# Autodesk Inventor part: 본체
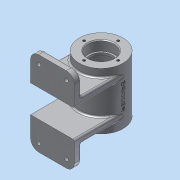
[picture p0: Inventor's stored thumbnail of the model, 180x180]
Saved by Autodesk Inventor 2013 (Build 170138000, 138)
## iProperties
Created: 2017-02
Part Number: 본체
Material: 알루미늄 6061
Document SubType Name: Modeling
Designer: dgall
Density: 2.71 g/cm^3
Mass: 356.371 g
Surface Area: 423.658 cm^2
Volume: 131.502 cm^3
Author: dgall
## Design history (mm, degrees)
sketch "스케치1"
  geometry: C1 r 27 at (0, 0); 1 further point
  constraints: 1 centre point, 1 coincident
  dimensions: "d0" = 54 diameter of C1
extrude "돌출1" new body sketch "스케치1" stored distance "d2" = 70; taper "d3" = 0 deg
sketch "스케치2"
  geometry: L1 (-52, 52)-(-60, 52); L2 (-60, 52)-(-60, 17); L3 (-60, 17)-(-52, 17); L4 (-52, 17)-(-52, 52); 1 further point
  constraints: 8 end point, 2 parallel, 1 horizontal, 1 perpendicular
  dimensions: "d4" = 17 distance from line of L3 point (0, 0); "d5" = 52 distance from line of L1 point (0, 0); "d6" = 8 distance of L1.start L1.end; "d7" = 60 distance from line of point (0, 0) L2
extrude "돌출2" join sketch "스케치2" stored distance "d8" = 54; taper "d9" = 0 deg
node "작업 평면1"
sketch "스케치3"
  geometry: L1 (27, -52)-(-27, -52) reference; L2 (-27, 0)-(-27, -52); L3 (27, 0)-(27, -52); A1 r 27 centre (0, 0) between (-27, 0) and (27, 0) reference; 1 further point
  constraints: 4 end point, 2 point on circle, 2 tangent, 1 parallel, 1 perpendicular
extrude "돌출3" join sketch "스케치3" distance "d11" = 8; taper "d12" = 0 deg
fillet "모깎기1" dims "d13" = 10
node "작업 평면2"
sketch "스케치4"
  geometry: L1 (27, 35)-(-27, 35) reference; C1 r 5 at (0, 10); 1 further point
  constraints: 1 centre point, 1 vertical alignment
  dimensions: "d15" = 25 distance from line of C1.centre L1; "d31" = 10 diameter of C1
extrude "돌출4" join sketch "스케치4" stored distance "d16" = 8; taper "d17" = 0 deg
sketch "스케치5"
  geometry: L1 (0, 0)-(-16.339, -25.16); L2 (0, 0)-(0, -27); 1 further point
  constraints: 4 end point, 1 vertical, 1 vertical alignment, 1 other
  dimensions: "d18" = 33 deg angle of L1 L2; "d19" = 30 distance of L1.start L1.end
node "작업 평면3"
sketch "스케치6"
  geometry: C1 r 6 at (0, 0); 1 further point
  constraints: 1 centre point, 1 coincident
  dimensions: "d20" = 12 diameter of C1
extrude "돌출5" join sketch "스케치6" stored distance "d22" = 8; taper "d23" = 0 deg
sketch "스케치7"
  geometry: L1 (27, 35)-(-27, 35) reference; L2 (-27, -35)-(27, -35) reference; L3 (0, 35)-(0, -35); L4 (0, 35)-(16, 35); L5 (16, 35)-(16, 23); L6 (16, 23)-(14, 23); L7 (14, 23)-(14, 20); L8 (14, 20)-(22, 20); L9 (22, 20)-(22, -20); L10 (22, -20)-(14, -20); L11 (14, -20)-(14, -23); L12 (14, -23)-(16, -23); L13 (16, -23)-(16, -35); 1 further point
  constraints: 22 end point, 6 parallel, 3 perpendicular, 2 collinear, 2 midpoint, 2 point on line, 2 vertical alignment
  dimensions: "d24" = 12 distance of L4.end L5.end; "d26" = 3 distance of L6.end L7.end; "d27" = 28 diameter of L7 L3; "d28" = 32 diameter of L5 L3; "d29" = 44 diameter of L9 L3
revolve "회전1" sketch "스케치7" stored, may be unused: angle "d30" = 90 deg
hole "구멍1" diameter "d34" = 5.188; stored, may be unused: countersink angle "d38" = 90 deg, drill point angle "d40" = 118 deg; dims "d32" = 10, "d33" = 10, "d35" = 6, "d36" = 4, "d37" = 2, "d39" = 8
hole "구멍2" diameter "d43" = 5.188; stored, may be unused: countersink angle "d47" = 90 deg, drill point angle "d49" = 118 deg; dims "d41" = 10, "d42" = 10, "d44" = 6, "d45" = 4, "d46" = 2, "d48" = 8
sketch "스케치8"
  geometry: C1 r 16 at (0, 0) reference; C2 r 14 at (0, 0) reference; 1 further point
  constraints: 1 vertical alignment
  dimensions: "d50" = 21 distance of point (0, 21) C2.centre
hole "구멍3" sketch "스케치8" at (0, 21) diameter "d51" = 3.242; stored, may be unused: countersink angle "d55" = 90 deg, drill point angle "d57" = 118 deg; dims "d52" = 8, "d53" = 4, "d54" = 2, "d56" = 10
sketch "스케치9"
  geometry: L1 (10, 22.196)-(14.5, 19.598); L2 (14.5, 19.598)-(14.5, 14.402); L3 (14.5, 14.402)-(10, 11.804); L4 (10, 11.804)-(5.5, 14.402); L5 (5.5, 14.402)-(5.5, 19.598); L6 (5.5, 19.598)-(10, 22.196); C1 r 4.5 at (10, 17); A1 r 10 centre (10, 17) between (10, 27) and (0, 17) reference; 2 further points
  constraints: 12 end point, 2 coincident, 1 centre point, 1 tangent, 1 vertical alignment, 13 other
  dimensions: "d61" = 9 diameter of C1
extrude "돌출6" cut sketch "스케치9" distance "d63" = 3; taper "d64" = 0 deg
sketch "스케치10"
  geometry: A1 r 10 centre (10, 17) between (10, 27) and (0, 17) reference; 1 further point
hole "구멍4" sketch "스케치10" at (10, 17) diameter "d65" = 5; stored, may be unused: countersink angle "d69" = 90 deg, drill point angle "d71" = 118 deg; dims "d66" = 8, "d67" = 4, "d68" = 2, "d70" = 10
chamfer "모따기1" distance "d78" = 1; stored, may be unused: second distance "d79" = 2, angle "d80" = 45 deg
fillet "모깎기2" dims "d81" = 0.3, "d82" = 3
fillet "모깎기3" dims "d83" = 2
fillet "모깎기4" dims "d84" = 2
fillet "모깎기5" dims "d85" = 2
fillet "모깎기6" dims "d86" = 2
node "작업 평면4"
sketch "스케치11"
  geometry: L1 (27, 35)-(-27, 35) reference; 2 further points
  constraints: 1 other
  dimensions: "d88" = 35 distance from line of point (0, 0) L1; "d89" = 27 horizontal distance of point (0, 0) L1.start
feature "엠보싱1" sketch "스케치11" dims "d90" = 0.5, "d91" = 0
node "솔리드1"
mirror "대칭1"
pattern_circular "원형 패턴1" dims angle "d59" = 360 deg
mirror "대칭2"
pattern_linear "직사각형 패턴1" dims "d74" = 34, "d77" = 84
other parameters: "d10" = 17, "d14" = 32
